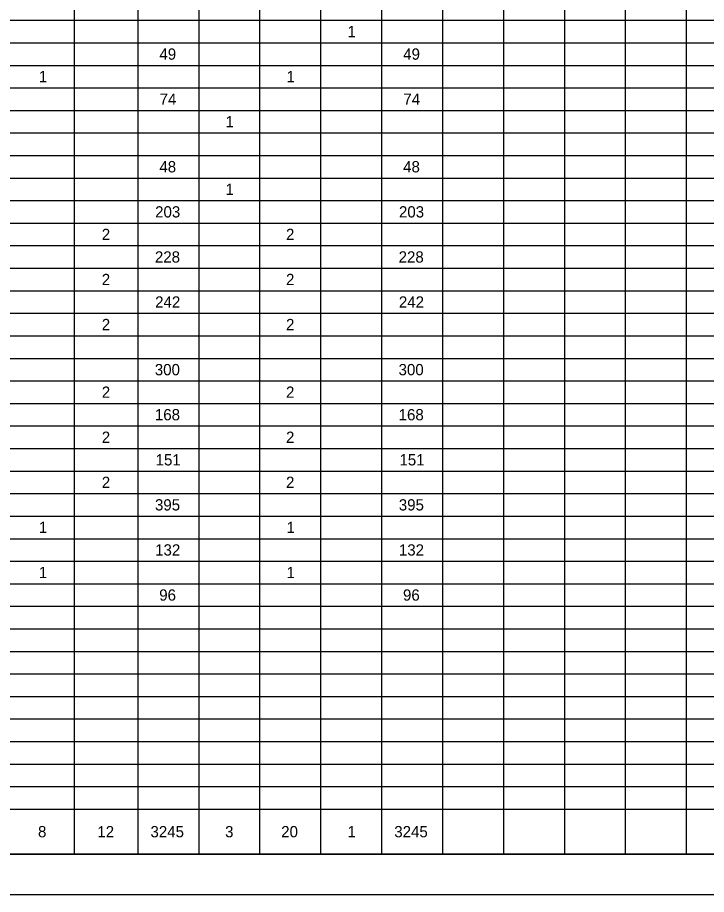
# Model space of a CAD drawing. Extents: x 0 to 34, y 0 to 22.
# Drawn here: x 16.87 to 25.44, y 0 to 10.89 of the extents above; entities that cross this region are included whole.
import ezdxf

# ---------------------------------------------------------------- set-up
doc = ezdxf.new("R2010")
doc.units = 0
for name, color, linetype in [('SH_Border', 7, 'Continuous'), ('SH_Cut_Line', 7, 'Continuous'), ('SH_Text', 7, 'Continuous')]:
    doc.layers.add(name, color=color, linetype=linetype)

msp = doc.modelspace()

# ---------------------------------------------------------------- linework, layer by layer
at = {"layer": 'SH_Border'}
msp.add_lwpolyline([(1.5, 21.5), (33.5, 21.5), (33.5, 0.5), (1.5, 0.5)], close=True, dxfattribs=at)
at = {"layer": 'SH_Cut_Line'}
msp.add_lwpolyline([(0, 0), (34, 0), (34, 22), (0, 22)], close=True, dxfattribs=at)
at = {"layer": 'SH_Text'}
for p, q in [((17.575, 21.5), (17.575, 0.5)), ((18.366, 21.5), (18.366, 0.5)), ((19.124, 21.5), (19.124, 0.5)), ((19.881, 21.5), (19.881, 0.5)), ((20.639, 21.5), (20.639, 0.5)), ((21.396, 21.5), (21.396, 0.5)), ((22.154, 21.5), (22.154, 0.5)), ((22.912, 21.5), (22.912, 0.5)), ((23.669, 21.5), (23.669, 0.5)), ((24.427, 21.5), (24.427, 0.5)), ((25.185, 21.5), (25.185, 0.5)), ((1.5, 10.86), (31.987, 10.86)), ((1.5, 10.58), (31.987, 10.58)), ((1.5, 10.3), (31.987, 10.3)), ((1.5, 10.02), (31.987, 10.02)), ((1.5, 9.74), (31.987, 9.74)), ((1.5, 9.46), (31.987, 9.46)), ((1.5, 9.18), (31.987, 9.18)), ((1.5, 8.9), (31.987, 8.9)), ((1.5, 8.62), (31.987, 8.62)), ((1.5, 8.34), (31.987, 8.34)), ((1.5, 8.06), (31.987, 8.06)), ((1.5, 7.78), (31.987, 7.78)), ((1.5, 7.5), (31.987, 7.5)), ((1.5, 7.22), (31.987, 7.22)), ((1.5, 6.94), (31.987, 6.94)), ((1.5, 6.66), (31.987, 6.66)), ((1.5, 6.38), (31.987, 6.38)), ((1.5, 6.1), (31.987, 6.1)), ((1.5, 5.82), (31.987, 5.82)), ((1.5, 5.54), (31.987, 5.54)), ((1.5, 5.26), (31.987, 5.26)), ((1.5, 4.98), (31.987, 4.98)), ((1.5, 4.7), (31.987, 4.7)), ((1.5, 4.42), (31.987, 4.42)), ((1.5, 4.14), (31.987, 4.14)), ((1.5, 3.86), (31.987, 3.86)), ((1.5, 3.58), (31.987, 3.58)), ((1.5, 3.3), (31.987, 3.3)), ((1.5, 3.02), (31.987, 3.02)), ((1.5, 2.74), (31.987, 2.74)), ((1.5, 2.46), (31.987, 2.46)), ((1.5, 2.18), (31.987, 2.18)), ((1.5, 1.9), (31.987, 1.9)), ((1.5, 1.62), (31.987, 1.62)), ((1.5, 1.34), (31.987, 1.34)), ((1.5, 1.06), (31.987, 1.06)), ((1.5, 0.5), (31.987, 0.5))]:
    msp.add_line(p, q, dxfattribs=at)

# ---------------------------------------------------------------- texts
for s, p in [('1', (20.973, 10.65)), ('49', (18.635, 10.37)), ('49', (21.666, 10.37)), ('1', (17.135, 10.09)), ('1', (20.215, 10.09)), ('74', (18.638, 9.81)), ('74', (21.668, 9.81)), ('1', (19.457, 9.53)), ('48', (18.635, 8.97)), ('48', (21.665, 8.97)), ('1', (19.457, 8.69)), ('203', (18.582, 8.41)), ('203', (21.613, 8.41)), ('2', (17.919, 8.13)), ('2', (20.209, 8.13)), ('228', (18.579, 7.85)), ('228', (21.609, 7.85)), ('2', (17.919, 7.57)), ('2', (20.209, 7.57)), ('242', (18.582, 7.29)), ('242', (21.612, 7.29)), ('2', (17.919, 7.01)), ('2', (20.209, 7.01)), ('300', (18.578, 6.45)), ('300', (21.608, 6.45)), ('2', (17.919, 6.17)), ('2', (20.209, 6.17)), ('168', (18.579, 5.89)), ('168', (21.609, 5.89)), ('2', (17.919, 5.61)), ('2', (20.209, 5.61)), ('151', (18.588, 5.33)), ('151', (21.619, 5.33)), ('2', (17.919, 5.05)), ('2', (20.209, 5.05)), ('395', (18.58, 4.77)), ('395', (21.611, 4.77)), ('1', (17.135, 4.49)), ('1', (20.215, 4.49)), ('132', (18.582, 4.21)), ('132', (21.612, 4.21)), ('1', (17.135, 3.93)), ('1', (20.215, 3.93)), ('96', (18.633, 3.65)), ('96', (21.663, 3.65)), ('8', (17.126, 0.71)), ('12', (17.864, 0.71)), ('3245', (18.524, 0.71)), ('3', (19.452, 0.71)), ('20', (20.149, 0.71)), ('1', (20.973, 0.71)), ('3245', (21.555, 0.71))]:
    msp.add_text(s, height=0.14, dxfattribs=at).set_placement(p)

doc.saveas('drawing.dxf')
